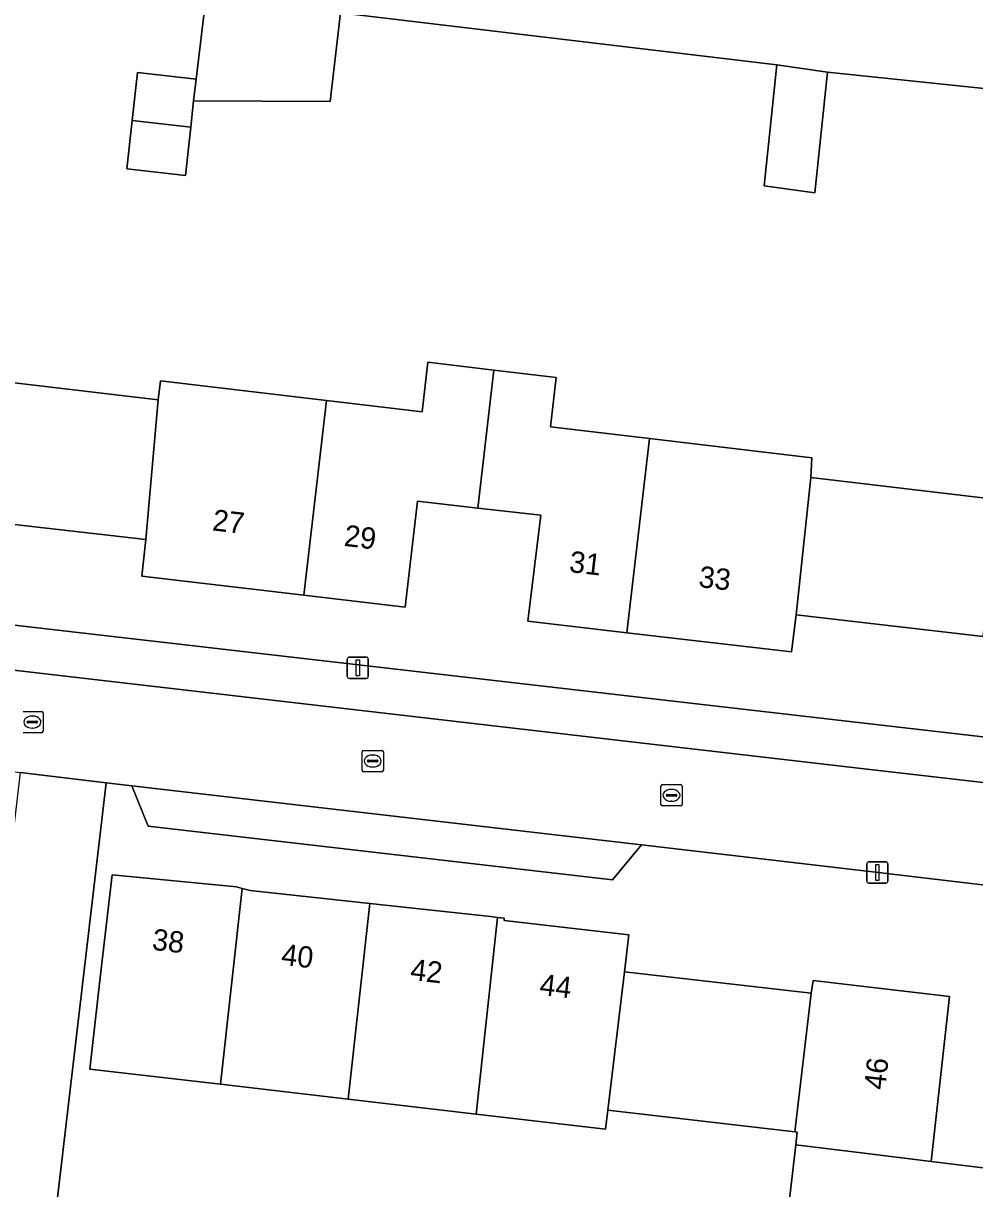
# Model space of a CAD drawing. Extents: x 161241 to 161758, y 384138 to 384885.
# Drawn here: x 161460.5 to 161505.2, y 384397.6 to 384452.3 of the extents above; entities that cross this region are included whole.
import ezdxf

# ---------------------------------------------------------------- set-up
doc = ezdxf.new("R2010")
doc.units = 0
for name, color, linetype in [('IMGEO_Erf', 7, 'Continuous'), ('IMGEO_Kolk', 7, 'Continuous'), ('IMGEO_Lichtmast', 7, 'Continuous'), ('IMGEO_Pand', 7, 'Continuous'), ('IMGEO_Pand_nummerreeks', 7, 'Continuous'), ('IMGEO_Parkeervlak_open', 7, 'Continuous'), ('IMGEO_Rijbaan_lokaal_open', 7, 'Continuous'), ('IMGEO_Voetpad_open', 7, 'Continuous')]:
    doc.layers.add(name, color=color, linetype=linetype)

msp = doc.modelspace()

# ---------------------------------------------------------------- linework, layer by layer
at = {"layer": 'IMGEO_Erf'}
for points in [[(161505.583, 384423.539), (161496.808, 384424.548), (161496.597, 384422.814), (161488.87, 384423.713), (161484.22, 384424.254), (161484.829, 384429.232), (161481.869, 384429.57), (161479.043, 384429.893), (161478.461, 384424.915), (161473.71, 384425.475), (161466.1, 384426.371), (161466.285, 384428.091), (161457.502, 384429.091), (161457.458, 384428.498), (161451.03, 384429.277), (161451.926, 384437.019), (161449.164, 384437.343), (161449.889, 384443.443), (161450.602, 384449.443), (161451.289, 384455.23)], [(161460.318, 384454.435), (161459.607, 384448.436), (161458.896, 384442.435), (161458.166, 384436.284), (161458.095, 384435.682), (161458.25, 384435.664), (161466.874, 384434.642), (161466.982, 384435.546), (161474.774, 384434.622), (161479.257, 384434.091), (161479.533, 384436.415), (161482.623, 384436.049), (161485.551, 384435.702), (161485.276, 384433.379), (161489.93, 384432.827), (161497.551, 384431.924), (161497.509, 384431.003), (161506.232, 384429.97)], [(161475.421, 384452.824), (161474.948, 384448.66), (161468.535, 384448.685), (161468.398, 384447.453), (161468.146, 384445.187), (161465.395, 384445.492), (161465.647, 384447.761), (161465.898, 384450.015), (161468.649, 384449.709), (161469.103, 384453.506)], [(161508.484, 384448.961), (161498.29, 384450.04), (161497.687, 384444.367), (161495.312, 384444.702), (161495.914, 384450.374), (161475.421, 384452.824)], [(161446.947, 384425.581), (161500, 384419.47), (161517.124, 384417.504)], [(161496.077, 384393.488), (161496.797, 384399.672), (161496.867, 384400.269), (161496.756, 384400.282), (161487.973, 384401.305), (161487.865, 384400.411), (161481.793, 384401.118), (161475.795, 384401.817), (161469.798, 384402.515), (161463.655, 384403.231), (161464.139, 384407.383), (161464.717, 384412.349), (161470.544, 384411.783), (161470.805, 384411.713), (161471.188, 384411.61), (161476.802, 384411.001), (161482.46, 384410.387), (161482.803, 384410.344), (161483.105, 384410.307), (161483.102, 384410.205), (161488.967, 384409.525), (161488.755, 384407.787), (161497.514, 384406.788), (161497.619, 384407.389), (161500, 384407.107), (161504.018, 384406.63), (161503.145, 384398.895), (161505.841, 384398.564)]]:
    msp.add_lwpolyline(points, dxfattribs=at)
msp.add_lwpolyline([(161510.318, 384411.321), (161500, 384412.531), (161489.559, 384413.756), (161488.192, 384412.116), (161466.402, 384414.639), (161465.637, 384416.532), (161464.436, 384416.673), (161460.643, 384384.386), (161461.694, 384384.264), (161461.77, 384385.111), (161461.973, 384387.389), (161464.245, 384387.187), (161463.961, 384384), (161506.638, 384379.095)], close=True, dxfattribs=at)
at = {"layer": 'IMGEO_Kolk'}
for p, q in [((161460.541, 384420.02), (161461.393, 384420.02)), ((161460.954, 384419.8), (161460.979, 384419.8)), ((161461.467, 384419.946), (161461.467, 384419.094)), ((161460.725, 384419.514), (161460.725, 384419.526)), ((161461.163, 384419.477), (161460.765, 384419.477)), ((161460.768, 384419.563), (161461.166, 384419.563)), ((161460.977, 384419.24), (161460.952, 384419.24)), ((161461.209, 384419.526), (161461.209, 384419.514)), ((161461.393, 384419.02), (161460.541, 384419.02)), ((161476.514, 384418.19), (161477.366, 384418.19)), ((161476.439, 384417.264), (161476.439, 384418.116)), ((161476.698, 384417.684), (161476.698, 384417.696)), ((161477.136, 384417.647), (161476.738, 384417.647)), ((161476.741, 384417.733), (161477.139, 384417.733)), ((161476.927, 384417.97), (161476.952, 384417.97)), ((161477.182, 384417.696), (161477.182, 384417.684)), ((161477.44, 384418.116), (161477.44, 384417.264)), ((161477.366, 384417.19), (161476.514, 384417.19)), ((161476.95, 384417.41), (161476.925, 384417.41)), ((161490.463, 384415.656), (161490.463, 384416.508)), ((161490.538, 384416.582), (161491.39, 384416.582)), ((161491.464, 384416.508), (161491.464, 384415.656)), ((161490.722, 384416.076), (161490.722, 384416.088)), ((161491.16, 384416.039), (161490.762, 384416.039)), ((161490.765, 384416.125), (161491.163, 384416.125)), ((161490.951, 384416.362), (161490.976, 384416.362)), ((161491.206, 384416.088), (161491.206, 384416.076)), ((161491.39, 384415.582), (161490.538, 384415.582)), ((161490.974, 384415.802), (161490.949, 384415.802))]:
    msp.add_line(p, q, dxfattribs=at)
for points in [[(161460.541, 384420.02), (161461.393, 384420.02)], [(161461.467, 384419.946), (161461.467, 384419.094)], [(161461.393, 384419.02), (161460.541, 384419.02)], [(161476.514, 384418.19), (161477.366, 384418.19)], [(161476.439, 384417.264), (161476.439, 384418.116)], [(161477.44, 384418.116), (161477.44, 384417.264)], [(161477.366, 384417.19), (161476.514, 384417.19)], [(161490.463, 384415.656), (161490.463, 384416.508)], [(161490.538, 384416.582), (161491.39, 384416.582)], [(161491.464, 384416.508), (161491.464, 384415.656)], [(161491.39, 384415.582), (161490.538, 384415.582)]]:
    msp.add_lwpolyline(points, dxfattribs=at)
for centre, radius, start, end in [((161461.391, 384419.944), 0.0765, 1.552, 88.448), ((161461.391, 384419.944), 0.0765, 1.552, 88.448), ((161460.765, 384419.523), 0.0403, 85.8775, 175.7526), ((161460.762, 384419.513), 0.0366, 178.938, 274.7102), ((161461.166, 384419.52), 0.043, 264.8664, 352.4533), ((161461.17, 384419.525), 0.0386, 1.7309, 96.639), ((161461.391, 384419.096), 0.0765, 271.552, 358.448), ((161461.391, 384419.096), 0.0765, 271.552, 358.448), ((161476.516, 384418.114), 0.0765, 91.552, 178.448), ((161476.516, 384418.114), 0.0765, 91.552, 178.448), ((161477.364, 384418.114), 0.0765, 1.552, 88.448), ((161477.364, 384418.114), 0.0765, 1.552, 88.448), ((161476.738, 384417.693), 0.0403, 85.8775, 175.7526), ((161476.735, 384417.683), 0.0366, 178.938, 274.7102), ((161477.139, 384417.69), 0.043, 264.8664, 352.4533), ((161477.143, 384417.695), 0.0386, 1.7309, 96.639), ((161476.516, 384417.266), 0.0765, 181.552, 268.448), ((161476.516, 384417.266), 0.0765, 181.552, 268.448), ((161477.364, 384417.266), 0.0765, 271.552, 358.448), ((161477.364, 384417.266), 0.0765, 271.552, 358.448), ((161490.54, 384416.506), 0.0765, 91.552, 178.448), ((161490.54, 384416.506), 0.0765, 91.552, 178.448), ((161491.388, 384416.506), 0.0765, 1.552, 88.448), ((161491.388, 384416.506), 0.0765, 1.552, 88.448), ((161490.762, 384416.085), 0.0403, 85.8775, 175.7526), ((161490.759, 384416.075), 0.0366, 178.938, 274.7102), ((161491.163, 384416.082), 0.043, 264.8664, 352.4533), ((161491.167, 384416.087), 0.0386, 1.7309, 96.639), ((161490.54, 384415.658), 0.0765, 181.552, 268.448), ((161490.54, 384415.658), 0.0765, 181.552, 268.448), ((161491.388, 384415.658), 0.0765, 271.552, 358.448), ((161491.388, 384415.658), 0.0765, 271.552, 358.448)]:
    msp.add_arc(centre, radius, start, end, dxfattribs=at)
for centre, major_axis, ratio, start_param, end_param in [((161460.953, 384419.52), (-0.387, 0.002), 0.722429, 4.712389, 7.853982), ((161460.978, 384419.52), (-0.39, 0.002), 0.717154, 1.570796, 4.712389), ((161476.926, 384417.69), (-0.387, 0.002), 0.722429, 4.712389, 7.853982), ((161476.951, 384417.69), (-0.39, 0.002), 0.717154, 1.570796, 4.712389), ((161490.95, 384416.082), (-0.387, 0.002), 0.722429, 4.712389, 7.853982), ((161490.975, 384416.082), (-0.39, 0.002), 0.717154, 1.570796, 4.712389)]:
    msp.add_ellipse(centre, major_axis=major_axis, ratio=ratio, start_param=start_param, end_param=end_param, dxfattribs=at)
at = {"layer": 'IMGEO_Lichtmast'}
for p, q in [((161475.843, 384422.568), (161476.633, 384422.568)), ((161476.633, 384422.568), (161475.843, 384422.568)), ((161475.743, 384421.668), (161475.743, 384422.468)), ((161475.743, 384422.468), (161475.743, 384421.668)), ((161476.733, 384422.468), (161476.733, 384421.668)), ((161476.733, 384421.668), (161476.733, 384422.468)), ((161476.633, 384421.568), (161475.843, 384421.568)), ((161475.843, 384421.568), (161476.633, 384421.568)), ((161500.128, 384412.06), (161500.128, 384412.86)), ((161500.128, 384412.86), (161500.128, 384412.06)), ((161500.228, 384412.96), (161501.018, 384412.96)), ((161501.018, 384412.96), (161500.228, 384412.96)), ((161501.118, 384412.86), (161501.118, 384412.06)), ((161501.118, 384412.06), (161501.118, 384412.86)), ((161501.018, 384411.96), (161500.228, 384411.96)), ((161500.228, 384411.96), (161501.018, 384411.96))]:
    msp.add_line(p, q, dxfattribs=at)
for points in [[(161476.163, 384422.443), (161476.313, 384422.443), (161476.313, 384421.693), (161476.163, 384421.693), (161476.163, 384422.443)], [(161500.548, 384412.835), (161500.698, 384412.835), (161500.698, 384412.085), (161500.548, 384412.085), (161500.548, 384412.835)]]:
    msp.add_lwpolyline(points, dxfattribs=at)
for centre, start, end in [((161475.843, 384422.468), 90, 180), ((161475.843, 384422.468), 90, 180), ((161476.633, 384422.468), 0, 90), ((161476.633, 384422.468), 360, 90), ((161475.843, 384421.668), 180, 270), ((161475.843, 384421.668), 180, 270), ((161476.633, 384421.668), 270, 0), ((161476.633, 384421.668), 270, 0), ((161500.228, 384412.86), 90, 180), ((161500.228, 384412.86), 90, 180), ((161501.018, 384412.86), 0, 90), ((161501.018, 384412.86), 360, 90), ((161500.228, 384412.06), 180, 270), ((161500.228, 384412.06), 180, 270), ((161501.018, 384412.06), 270, 0), ((161501.018, 384412.06), 270, 0)]:
    msp.add_arc(centre, 0.1, start, end, dxfattribs=at)
at = {"layer": 'IMGEO_Pand'}
for points in [[(161468.649, 384449.709), (161465.898, 384450.015), (161465.647, 384447.761), (161468.398, 384447.453), (161468.535, 384448.685)], [(161498.29, 384450.04), (161495.914, 384450.374), (161495.312, 384444.702), (161497.687, 384444.367)], [(161465.395, 384445.492), (161468.146, 384445.187), (161468.398, 384447.453), (161465.647, 384447.761)], [(161473.71, 384425.475), (161478.461, 384424.915), (161479.043, 384429.893), (161481.869, 384429.57), (161482.623, 384436.049), (161479.533, 384436.415), (161479.257, 384434.091), (161474.774, 384434.622)], [(161458.25, 384435.664), (161457.502, 384429.091), (161466.285, 384428.091), (161466.874, 384434.642)], [(161489.93, 384432.827), (161485.276, 384433.379), (161485.551, 384435.702), (161482.623, 384436.049), (161481.869, 384429.57), (161484.829, 384429.232), (161484.22, 384424.254), (161488.87, 384423.713)], [(161466.982, 384435.546), (161466.874, 384434.642), (161466.285, 384428.091), (161466.1, 384426.371), (161473.71, 384425.475), (161474.774, 384434.622)], [(161497.509, 384431.003), (161497.551, 384431.924), (161489.93, 384432.827), (161488.87, 384423.713), (161496.597, 384422.814), (161496.808, 384424.548)], [(161505.583, 384423.539), (161506.232, 384429.97), (161497.509, 384431.003), (161496.808, 384424.548)], [(161470.805, 384411.713), (161470.544, 384411.783), (161464.717, 384412.349), (161464.139, 384407.383), (161463.655, 384403.231), (161469.798, 384402.515)], [(161476.802, 384411.001), (161471.188, 384411.61), (161470.805, 384411.713), (161469.798, 384402.515), (161475.795, 384401.817)], [(161482.803, 384410.344), (161482.46, 384410.387), (161476.802, 384411.001), (161475.795, 384401.817), (161481.793, 384401.118)], [(161488.755, 384407.787), (161488.967, 384409.525), (161483.102, 384410.205), (161483.105, 384410.307), (161482.803, 384410.344), (161481.793, 384401.118), (161487.865, 384400.411), (161487.973, 384401.305)], [(161497.514, 384406.788), (161488.755, 384407.787), (161487.973, 384401.305), (161496.756, 384400.282)], [(161500, 384399.28), (161503.145, 384398.895), (161504.018, 384406.63), (161500, 384407.107), (161497.619, 384407.389), (161497.514, 384406.788), (161496.756, 384400.282), (161496.867, 384400.269), (161496.797, 384399.672)], [(161496.797, 384399.672), (161496.077, 384393.488), (161500, 384393.028), (161505.109, 384392.428), (161505.841, 384398.564), (161503.145, 384398.895), (161500, 384399.28)]]:
    msp.add_lwpolyline(points, close=True, dxfattribs=at)
at = {"layer": 'IMGEO_Parkeervlak_open'}
msp.add_lwpolyline([(161489.559, 384413.756), (161465.637, 384416.532), (161466.402, 384414.639), (161488.192, 384412.116)], close=True, dxfattribs=at)
at = {"layer": 'IMGEO_Rijbaan_lokaal_open'}
for points in [[(161469.103, 384453.506), (161468.649, 384449.709), (161468.535, 384448.685), (161474.948, 384448.66), (161475.421, 384452.824), (161495.914, 384450.374), (161498.29, 384450.04), (161508.484, 384448.961), (161517.687, 384447.884), (161520.657, 384447.535), (161520.752, 384448.346), (161517.847, 384448.768), (161510.292, 384449.829), (161513.81, 384486.25)], [(161516.896, 384415.376), (161500, 384417.331), (161455.361, 384422.51), (161454.814, 384417.799), (161459.347, 384417.271), (161460.391, 384417.148), (161464.436, 384416.673), (161465.637, 384416.532), (161489.559, 384413.756), (161500, 384412.531), (161510.318, 384411.321), (161514.204, 384410.875), (161523.243, 384409.923)], [(161506.638, 384379.095), (161463.961, 384384), (161461.689, 384384.202), (161461.694, 384384.264), (161460.643, 384384.386), (161464.436, 384416.673), (161460.391, 384417.148), (161456.596, 384384.852), (161428.41, 384388.19), (161425.953, 384388.43), (161423.606, 384388.659), (161423.913, 384391.799), (161424.15, 384393.701), (161415.847, 384394.67)]]:
    msp.add_lwpolyline(points, dxfattribs=at)
at = {"layer": 'IMGEO_Voetpad_open'}
msp.add_lwpolyline([(161427.439, 384427.904), (161410.092, 384429.939), (161407.225, 384430.276), (161404.443, 384430.602), (161399.514, 384431.19), (161393.511, 384431.885), (161387.488, 384432.576), (161336.535, 384438.485), (161336.257, 384436.376), (161382.402, 384431.06), (161401.922, 384428.768), (161404.653, 384428.447), (161443.686, 384423.864), (161452.639, 384422.825), (161455.361, 384422.51), (161500, 384417.331), (161516.896, 384415.376), (161517.124, 384417.504), (161500, 384419.47), (161446.947, 384425.581), (161440.852, 384426.331)], close=True, dxfattribs=at)

# ---------------------------------------------------------------- texts
at = {"layer": 'IMGEO_Pand_nummerreeks'}
for s, rotation, p in [('27', 353.2849, (161469.379, 384428.522)), ('29', 353.2776, (161475.56, 384427.795)), ('31', 353.3638, (161486.127, 384426.569)), ('33', 353.3637, (161492.204, 384425.862)), ('38', 353.3576, (161466.551, 384408.833)), ('40', 353.3576, (161472.613, 384408.127)), ('42', 353.3576, (161478.67, 384407.421)), ('44', 353.3594, (161484.735, 384406.715)), ('46', 83.5606, (161500.985, 384402.224))]:
    msp.add_text(s, height=1, rotation=rotation, dxfattribs=at).set_placement(p)

doc.saveas('drawing.dxf')
